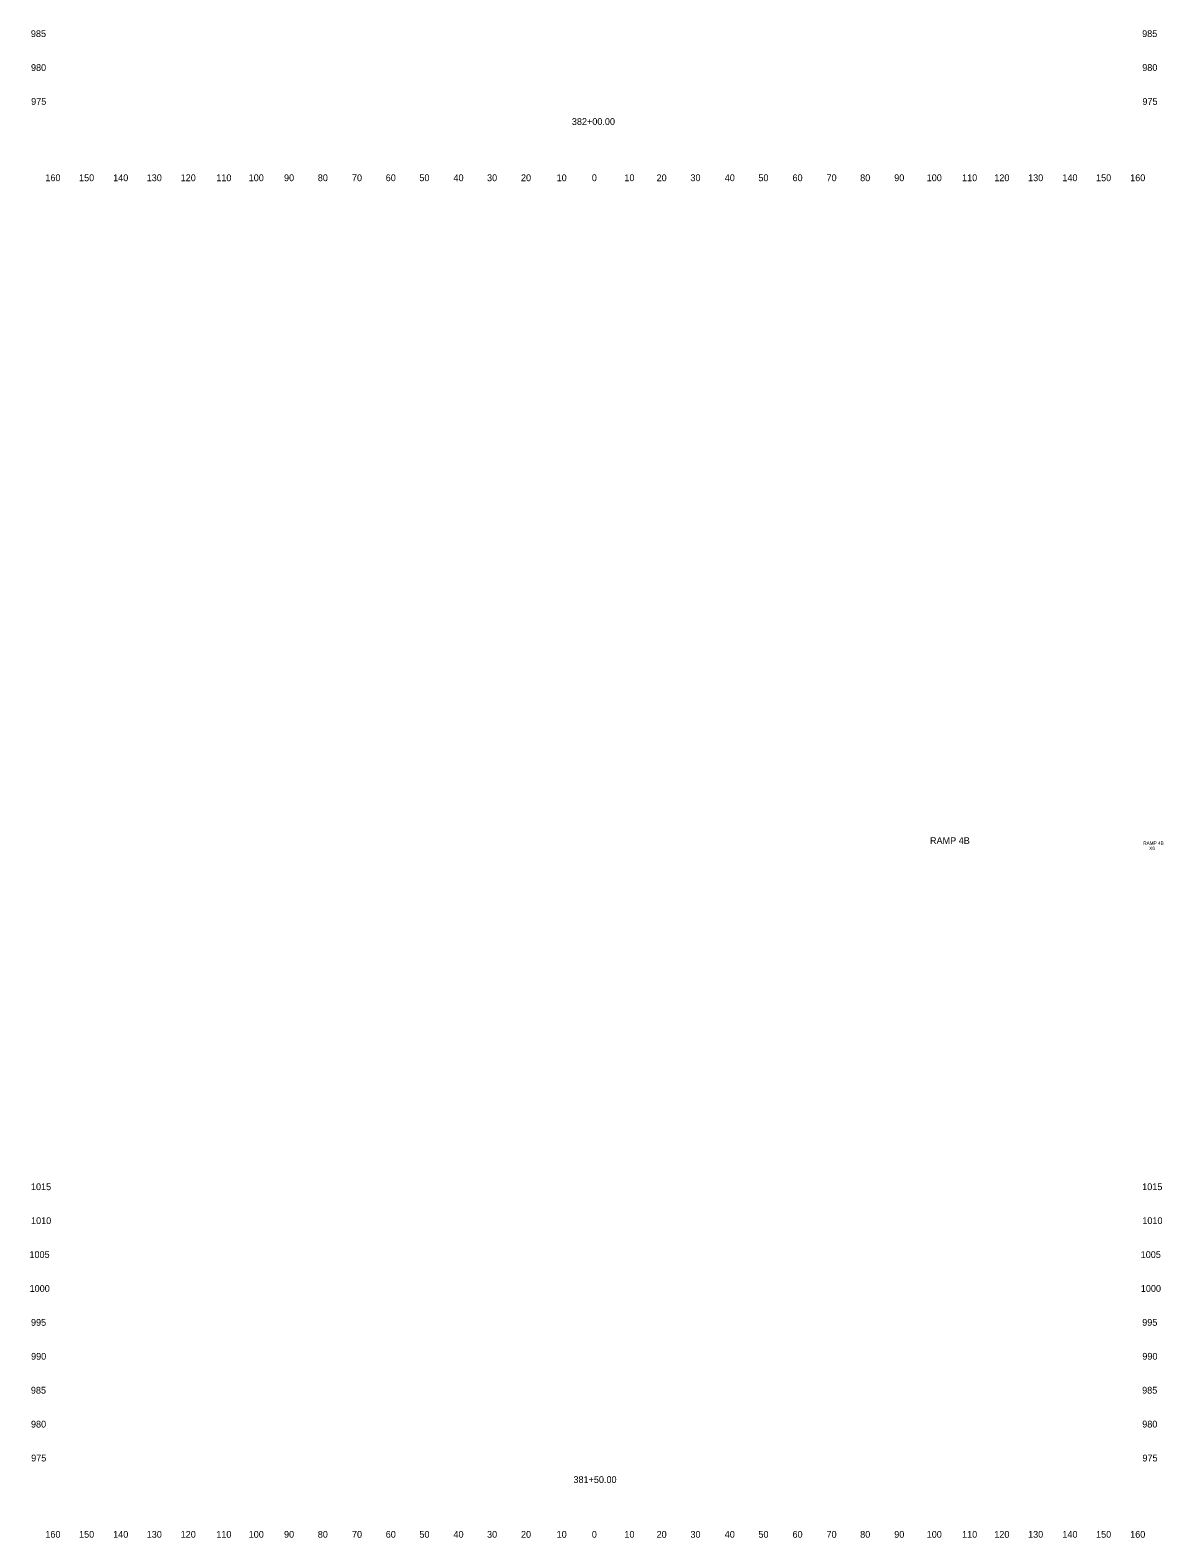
# Model space of a CAD drawing. Extents: x 4994 to 6358, y 4997 to 8804.
# Drawn here: x 4993.6 to 5327.7, y 6997.5 to 7442 of the extents above; entities that cross this region are included whole.
import ezdxf

# ---------------------------------------------------------------- set-up
doc = ezdxf.new("R2010")
doc.units = 0
for name, color, linetype in [('CLS_Search_Dist', 7, 'Continuous'), ('RD_XE_Ground', 7, 'Continuous'), ('UC_PD_Text', 7, 'Continuous')]:
    doc.layers.add(name, color=color, linetype=linetype)

msp = doc.modelspace()

# ---------------------------------------------------------------- texts
at = {"layer": 'CLS_Search_Dist'}
for s, p in [('985', (4993.83, 7440)), ('985', (5321.63, 7440)), ('980', (4993.86, 7430)), ('980', (5321.66, 7430)), ('975', (4993.91, 7420)), ('975', (5321.71, 7420)), ('160', (4998.1, 7397.5)), ('150', (5008.04, 7397.5)), ('140', (5018.1, 7397.5)), ('130', (5027.99, 7397.5)), ('120', (5038.01, 7397.5)), ('110', (5048.51, 7397.5)), ('100', (5058.07, 7397.5)), ('90', (5068.5, 7397.5)), ('80', (5078.46, 7397.5)), ('70', (5088.54, 7397.5)), ('60', (5098.5, 7397.5)), ('50', (5108.43, 7397.5)), ('40', (5118.5, 7397.5)), ('30', (5128.39, 7397.5)), ('20', (5138.4, 7397.5)), ('10', (5148.91, 7397.5)), ('0', (5159.3, 7397.5)), ('0', (5159.3, 7397.5)), ('10', (5168.91, 7397.5)), ('20', (5178.4, 7397.5)), ('30', (5188.39, 7397.5)), ('40', (5198.5, 7397.5)), ('50', (5208.43, 7397.5)), ('60', (5218.5, 7397.5)), ('70', (5228.54, 7397.5)), ('80', (5238.46, 7397.5)), ('90', (5248.5, 7397.5)), ('100', (5258.07, 7397.5)), ('110', (5268.51, 7397.5)), ('120', (5278.01, 7397.5)), ('130', (5287.99, 7397.5)), ('140', (5298.1, 7397.5)), ('150', (5308.04, 7397.5)), ('160', (5318.1, 7397.5)), ('1015', (4993.85, 7100)), ('1015', (5321.65, 7100)), ('1010', (4993.88, 7090)), ('1010', (5321.68, 7090)), ('1005', (4993.4, 7080)), ('1005', (5321.2, 7080)), ('1000', (4993.44, 7070)), ('1000', (5321.24, 7070)), ('995', (4993.86, 7060)), ('995', (5321.66, 7060)), ('990', (4993.89, 7050)), ('990', (5321.69, 7050)), ('985', (4993.83, 7040)), ('985', (5321.63, 7040)), ('980', (4993.86, 7030)), ('980', (5321.66, 7030)), ('975', (4993.91, 7020)), ('975', (5321.71, 7020)), ('160', (4998.1, 6997.5)), ('150', (5008.04, 6997.5)), ('140', (5018.1, 6997.5)), ('130', (5027.99, 6997.5)), ('120', (5038.01, 6997.5)), ('110', (5048.51, 6997.5)), ('100', (5058.07, 6997.5)), ('90', (5068.5, 6997.5)), ('80', (5078.46, 6997.5)), ('70', (5088.54, 6997.5)), ('60', (5098.5, 6997.5)), ('50', (5108.43, 6997.5)), ('40', (5118.5, 6997.5)), ('30', (5128.39, 6997.5)), ('20', (5138.4, 6997.5)), ('10', (5148.91, 6997.5)), ('0', (5159.3, 6997.5)), ('0', (5159.3, 6997.5)), ('10', (5168.91, 6997.5)), ('20', (5178.4, 6997.5)), ('30', (5188.39, 6997.5)), ('40', (5198.5, 6997.5)), ('50', (5208.43, 6997.5)), ('60', (5218.5, 6997.5)), ('70', (5228.54, 6997.5)), ('80', (5238.46, 6997.5)), ('90', (5248.5, 6997.5)), ('100', (5258.07, 6997.5)), ('110', (5268.51, 6997.5)), ('120', (5278.01, 6997.5)), ('130', (5287.99, 6997.5)), ('140', (5298.1, 6997.5)), ('150', (5308.04, 6997.5)), ('160', (5318.1, 6997.5))]:
    msp.add_text(s, height=2, dxfattribs=at).set_placement(p)
at = {"layer": 'RD_XE_Ground'}
for s, p in [('382+00.00', (5153.41, 7414.08)), ('381+50.00', (5153.88, 7013.65))]:
    msp.add_text(s, height=2, dxfattribs=at).set_placement(p)
at = {"layer": 'UC_PD_Text'}
for s, height, p in [('RAMP 4B', 2, (5259.05, 7202.06)), ('RAMP 4B', 1, (5321.94, 7201.8)), ('X6', 1, (5323.71, 7200.3))]:
    msp.add_text(s, height=height, dxfattribs=at).set_placement(p)

doc.saveas('drawing.dxf')
